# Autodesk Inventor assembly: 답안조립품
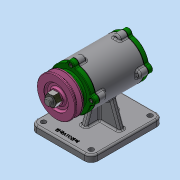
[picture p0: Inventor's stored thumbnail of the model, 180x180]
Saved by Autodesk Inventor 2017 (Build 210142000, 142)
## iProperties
Part Number: 답안조립품
Material: 일반
Document SubType Name: Assembly
Designer: MRC
Author: MRC
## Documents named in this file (12)
- C:\Users\MRC\Desktop\720716V1001\답안조립품.iam
- C:\Users\MRC\Desktop\720716V1001\본체.ipt
- C:\Users\MRC\Desktop\720716V1001\V-벨트풀리.ipt
- C:\Users\MRC\Desktop\720716V1001\개스킷.ipt
- C:\Users\MRC\Desktop\720716V1001\너트 M12 x 1.25.ipt
- C:\Users\MRC\Desktop\720716V1001\뒤커버.ipt
- C:\Users\MRC\Desktop\720716V1001\베어링 6204.ipt
- C:\Users\MRC\Desktop\720716V1001\볼트 M4 x 12.ipt
- C:\Users\MRC\Desktop\720716V1001\앞커버.ipt
- C:\Users\MRC\Desktop\720716V1001\오일 실.ipt
- C:\Users\MRC\Desktop\720716V1001\축.ipt
- C:\Users\MRC\Desktop\720716V1001\키 4 x 4.ipt
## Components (3 placed, 2 different names)
1. 개스킷:1
2. 개스킷:2
3. V-벨트풀리:1
